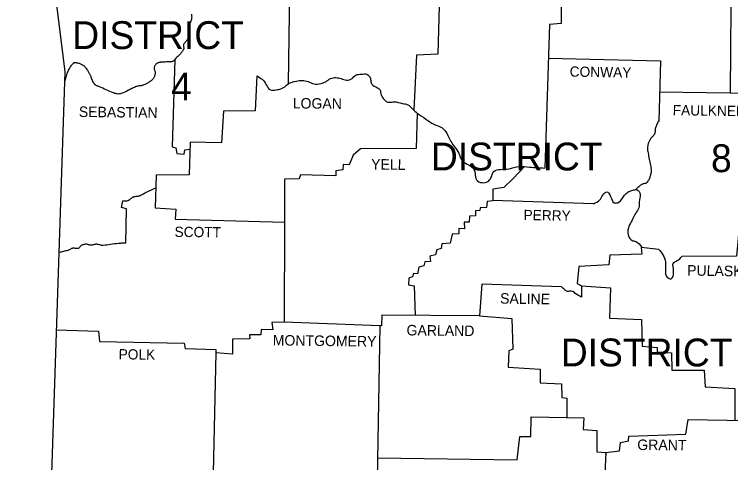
# Model space of a CAD drawing. Extents: x 1373878 to 1386598, y 1168333 to 1170533.
# Drawn here: x 1376295.6 to 1376588.9, y 1169955.3 to 1170138.8 of the extents above; entities that cross this region are included whole.
import ezdxf

# ---------------------------------------------------------------- set-up
doc = ezdxf.new("R2010")
doc.units = 0
doc.layers.add('1', color=7, linetype='Continuous')
doc.layers.add('Default', color=7, linetype='Continuous')

msp = doc.modelspace()

# ---------------------------------------------------------------- linework, layer by layer
at = {"layer": '1'}
msp.add_line((1376445.29, 1170011.31), (1376444.13, 1169948.51), dxfattribs=at)
for points in [[(1376295.59, 1170281.4), (1376316.29, 1170115.21), (1376307.29, 1169843.91)], [(1376599.19, 1170281.6), (1376599.39, 1170257.2), (1376597.69, 1170257.1), (1376597.99, 1170232.2), (1376590.99, 1170231.2), (1376591.59, 1170224.5), (1376593.99, 1170221.4), (1376593.79, 1170213.5), (1376580.19, 1170213), (1376579.69, 1170200.8), (1376567.29, 1170200.4), (1376566.69, 1170185.61), (1376567.39, 1170184.41), (1376567.69, 1170160.81), (1376589.09, 1170159.41), (1376588.79, 1170106.71), (1376605.79, 1170106.21), (1376605.79, 1170052.61), (1376592.39, 1170051.61), (1376591.39, 1170039.81), (1376568.89, 1170039.71)], [(1376408.49, 1170168.11), (1376407.79, 1170110.41)], [(1376394.89, 1170113.61), (1376394.19, 1170099.31), (1376381.19, 1170099.21), (1376380.49, 1170086.21), (1376367.59, 1170086.51), (1376367.19, 1170073.11), (1376353.69, 1170073.01), (1376353.29, 1170059.61), (1376361.79, 1170059.11), (1376361.49, 1170055.01), (1376406.23, 1170053.77)], [(1376406.23, 1170053.77), (1376406.09, 1170012.81), (1376401.09, 1170012.71), (1376401.49, 1170009.71), (1376396.69, 1170009.81), (1376396.59, 1170007.61), (1376391.89, 1170007.61), (1376391.99, 1170006.01), (1376384.99, 1170005.81), (1376384.89, 1169999.71), (1376378.09, 1170000.31), (1376376.99, 1169951.11), (1376338.49, 1169951.21), (1376337.59, 1169939.81), (1376338.99, 1169938.81), (1376338.89, 1169926.01), (1376310.06, 1169927.28)], [(1376559.49, 1170042.61), (1376552.29, 1170043.41), (1376552.59, 1170040.71), (1376539.49, 1170040.21), (1376539.09, 1170036.31), (1376526.79, 1170035.61), (1376526.09, 1170028.61), (1376527.89, 1170027.71), (1376527.89, 1170023.11)], [(1376519.69, 1170027.31), (1376486.99, 1170028.31), (1376486.09, 1170015.41), (1376446.09, 1170015.61), (1376445.93, 1170011.29)], [(1376537.79, 1169959.41), (1376543.39, 1169960.21), (1376543.79, 1169963.61), (1376547.09, 1169964.21), (1376547.29, 1169966.21), (1376570.59, 1169966.91), (1376571.49, 1169973.01), (1376595.39, 1169972.61)], [(1376537.79, 1169959.41), (1376536.59, 1169933.21), (1376535.69, 1169933.51), (1376535.79, 1169920.03)]]:
    msp.add_lwpolyline(points, dxfattribs=at)
for points in [[(1376394.89, 1170113.61), (1376397.09, 1170112.21), (1376398.79, 1170109.91), (1376400.29, 1170108.01), (1376402.79, 1170107.91), (1376404.79, 1170108.31), (1376407.79, 1170110.41)], [(1376559.49, 1170042.61), (1376561.19, 1170040.41), (1376562.19, 1170037.41), (1376562.19, 1170034.01), (1376562.99, 1170031.21), (1376564.59, 1170030.61), (1376565.59, 1170033.01), (1376565.39, 1170035.41), (1376565.39, 1170036.81), (1376567.09, 1170038.01), (1376568.89, 1170039.71)], [(1376527.89, 1170023.11), (1376525.29, 1170024.61), (1376523.79, 1170025.51), (1376522.19, 1170025.41), (1376520.89, 1170026.21), (1376519.69, 1170027.31)]]:
    msp.add_spline(points, degree=3, dxfattribs=at)
at = {"layer": 'Default'}
for points in [[(1376476.63, 1170162.03), (1376476.52, 1170142.44), (1376469.62, 1170142.34), (1376469.02, 1170122.44), (1376460.22, 1170122.14), (1376459.13, 1170099.7)], [(1376519.7, 1170161.68), (1376519.49, 1170135.11), (1376514.69, 1170134.71), (1376512.79, 1170075.91)], [(1376514.24, 1170120.81), (1376560.19, 1170119.71), (1376559.59, 1170095.01)], [(1376361.33, 1170120.28), (1376360.29, 1170084.61), (1376361.79, 1170084.21), (1376362.09, 1170081.81), (1376365.09, 1170081.61), (1376365.39, 1170083.31), (1376367.51, 1170083.66)], [(1376559.69, 1170107.11), (1376588.79, 1170106.71)], [(1376460.59, 1170098.31), (1376460.19, 1170083.91), (1376437.39, 1170083.81), (1376434.39, 1170081.21), (1376432.69, 1170077.21), (1376430.19, 1170077.41), (1376430.09, 1170075.11), (1376427.19, 1170074.81), (1376427.29, 1170072.71), (1376412.79, 1170073.11), (1376412.29, 1170071.51), (1376406.29, 1170071.31), (1376406.23, 1170053.77)], [(1376504.35, 1170076.44), (1376499.89, 1170071.61), (1376495.99, 1170067.91), (1376491.49, 1170067.21), (1376491.49, 1170062.51), (1376489.29, 1170062.21), (1376488.89, 1170059.81), (1376486.39, 1170059.61), (1376486.19, 1170058.51), (1376484.49, 1170058.41), (1376484.39, 1170056.31), (1376481.99, 1170056.21), (1376481.79, 1170053.81), (1376479.79, 1170053.81), (1376479.89, 1170051.01), (1376477.69, 1170051.21), (1376477.59, 1170049.01), (1376474.89, 1170048.81), (1376474.09, 1170045.21), (1376470.69, 1170044.91), (1376470.39, 1170042.91), (1376468.59, 1170042.41), (1376468.09, 1170040.31), (1376465.79, 1170039.81), (1376465.99, 1170037.71), (1376463.69, 1170037.51), (1376463.29, 1170035.91), (1376461.19, 1170035.31), (1376460.69, 1170032.61), (1376459.09, 1170032.71), (1376458.59, 1170031.31), (1376457.09, 1170030.81), (1376456.99, 1170028.11), (1376459.29, 1170027.71), (1376459.71, 1170015.54)], [(1376341.19, 1170045.11), (1376341.49, 1170059.21), (1376339.49, 1170059.81), (1376340.09, 1170062.51)], [(1376532.79, 1170061.31), (1376491.49, 1170062.61)], [(1376527.89, 1170027.65), (1376539.79, 1170026.91), (1376539.39, 1170014.41), (1376552.49, 1170013.91), (1376552.69, 1170003.01), (1376558.89, 1170002.51), (1376558.89, 1170000.61), (1376564.69, 1170000.21), (1376564.89, 1169993.21), (1376578.09, 1169993.21), (1376578.49, 1169986.31), (1376590.69, 1169985.71), (1376590.59, 1169972.69)], [(1376486.09, 1170015.41), (1376499.39, 1170014.31), (1376499.79, 1170001.71), (1376498.09, 1170001.11), (1376497.89, 1169994.41), (1376510.99, 1169993.51), (1376510.99, 1169988.01), (1376519.69, 1169987.51), (1376519.79, 1169982.01), (1376521.89, 1169981.71), (1376521.79, 1169973.81)], [(1376445.29, 1170011.31), (1376406.09, 1170012.81)], [(1376312.79, 1170009.71), (1376330.09, 1170009.11), (1376330.49, 1170004.91), (1376365.09, 1170004.21), (1376365.49, 1170002.01), (1376378.09, 1170001.61), (1376378.09, 1170000.31)], [(1376445.93, 1170011.29), (1376445.29, 1170011.31)], [(1376444.29, 1169957.31), (1376501.49, 1169956.51), (1376502.59, 1169966.01), (1376507.09, 1169966.01), (1376507.19, 1169974.01), (1376528.79, 1169973.71), (1376528.59, 1169968.91), (1376534.19, 1169968.51), (1376534.19, 1169959.71), (1376537.79, 1169959.41), (1376537.75, 1169958.5)]]:
    msp.add_lwpolyline(points, dxfattribs=at)
for points in [[(1376368.09, 1170138.81), (1376368.18, 1170138.28), (1376368.22, 1170137.75), (1376368.09, 1170136.71), (1376367.91, 1170136.15), (1376367.7, 1170135.61), (1376367.49, 1170135.06), (1376367.29, 1170134.51), (1376366.79, 1170132.61), (1376366.79, 1170131.99), (1376366.95, 1170131.36), (1376367.1, 1170130.73), (1376367.13, 1170130.42), (1376367.09, 1170130.11), (1376366.72, 1170129.08), (1376366.19, 1170128.11), (1376365.89, 1170127.69), (1376365.53, 1170127.31), (1376365.18, 1170126.92), (1376364.89, 1170126.51), (1376364.81, 1170126.03), (1376364.9, 1170125.51), (1376364.99, 1170124.98), (1376364.89, 1170124.51), (1376364.73, 1170124.23), (1376364.57, 1170123.95), (1376364.21, 1170123.41), (1376363.82, 1170122.89), (1376363.39, 1170122.41), (1376361.79, 1170120.81), (1376361.16, 1170120.09), (1376360.81, 1170119.76), (1376360.61, 1170119.62), (1376360.51, 1170119.56), (1376360.39, 1170119.51), (1376359.78, 1170119.34), (1376359.15, 1170119.3), (1376358.52, 1170119.31), (1376358.21, 1170119.32), (1376357.89, 1170119.31), (1376356.84, 1170119.26), (1376355.79, 1170119.21), (1376355.25, 1170119.15), (1376354.72, 1170119.04), (1376354.2, 1170118.84), (1376353.95, 1170118.69), (1376353.69, 1170118.51), (1376353.36, 1170118.18), (1376353.13, 1170117.81), (1376352.98, 1170117.42), (1376352.89, 1170117.01), (1376352.92, 1170116.43), (1376353.09, 1170115.86), (1376353.26, 1170115.28), (1376353.29, 1170114.71), (1376353.2, 1170114.14), (1376353.06, 1170113.58), (1376352.49, 1170112.51), (1376351.51, 1170111.54), (1376350.39, 1170110.81), (1376349.27, 1170110.19), (1376348.09, 1170109.71), (1376347.5, 1170109.58), (1376346.88, 1170109.53), (1376346.27, 1170109.47), (1376345.69, 1170109.31), (1376344.86, 1170108.92), (1376344.04, 1170108.52), (1376343.22, 1170108.11), (1376342.39, 1170107.71), (1376339.39, 1170106.41), (1376338.61, 1170106.22), (1376337.79, 1170106.21), (1376336.97, 1170106.35), (1376336.19, 1170106.61), (1376333.19, 1170107.91), (1376330.49, 1170109.11), (1376329.93, 1170109.34), (1376329.37, 1170109.59), (1376328.85, 1170109.89), (1376328.61, 1170110.08), (1376328.5, 1170110.19), (1376328.39, 1170110.31), (1376327.83, 1170111.17), (1376327.43, 1170112.11), (1376327.09, 1170113.07), (1376326.91, 1170113.55), (1376326.69, 1170114.01), (1376326.16, 1170115.01), (1376325.59, 1170116.01), (1376325.21, 1170116.57), (1376324.77, 1170117.09), (1376324.27, 1170117.56), (1376323.99, 1170117.79), (1376323.69, 1170118.01), (1376323.14, 1170118.32), (1376322.56, 1170118.54), (1376321.98, 1170118.69), (1376321.39, 1170118.81), (1376320.91, 1170118.9), (1376320.41, 1170118.95), (1376319.92, 1170118.88), (1376319.7, 1170118.78), (1376319.59, 1170118.7), (1376319.49, 1170118.61), (1376318.15, 1170116.82), (1376317.27, 1170114.96), (1376316.68, 1170113.05), (1376316.16, 1170111.11)], [(1376407.79, 1170110.41), (1376411.09, 1170111.51), (1376413.49, 1170111.71), (1376415.89, 1170111.31), (1376418.39, 1170110.31), (1376421.09, 1170110.51), (1376423.09, 1170111.21), (1376425.09, 1170112.51), (1376427.29, 1170112.91), (1376429.39, 1170112.51), (1376431.59, 1170111.91), (1376433.99, 1170112.61), (1376435.39, 1170113.91), (1376437.79, 1170114.31), (1376439.89, 1170114.31), (1376441.39, 1170112.61), (1376441.69, 1170110.81), (1376443.59, 1170109.11), (1376445.29, 1170108.01), (1376445.79, 1170105.91), (1376446.69, 1170104.41), (1376447.59, 1170103.41), (1376448.89, 1170102.81), (1376451.09, 1170103.01), (1376454.49, 1170102.31), (1376456.69, 1170101.81), (1376458.69, 1170100.11), (1376460.59, 1170098.31)], [(1376460.59, 1170098.31), (1376464.09, 1170095.91), (1376467.39, 1170093.81), (1376470.79, 1170092.31), (1376472.69, 1170090.11), (1376474.39, 1170086.71), (1376475.79, 1170084.61), (1376477.59, 1170082.01), (1376478.89, 1170079.11), (1376480.99, 1170077.51), (1376483.19, 1170076.11), (1376484.29, 1170073.61), (1376484.79, 1170071.11), (1376487.19, 1170069.91), (1376489.49, 1170070.41), (1376490.79, 1170071.91), (1376491.99, 1170074.51), (1376494.69, 1170075.31), (1376498.19, 1170075.61), (1376502.19, 1170076.51), (1376506.59, 1170076.31), (1376512.79, 1170075.91)], [(1376559.59, 1170095.01), (1376559.45, 1170095.05), (1376559.29, 1170094.92), (1376558.95, 1170094.31), (1376558.6, 1170093.48), (1376558.44, 1170093.07), (1376558.29, 1170092.71), (1376558.08, 1170091.95), (1376558, 1170091.18), (1376557.92, 1170090.42), (1376557.83, 1170090.06), (1376557.69, 1170089.71), (1376557.35, 1170089.2), (1376556.92, 1170088.75), (1376556.47, 1170088.3), (1376556.09, 1170087.81), (1376555.79, 1170087.28), (1376555.5, 1170086.74), (1376555.09, 1170085.61), (1376555.02, 1170085.25), (1376554.96, 1170084.88), (1376554.9, 1170084.15), (1376554.9, 1170083.43), (1376554.99, 1170082.71), (1376555.49, 1170080.11), (1376555.99, 1170077.61), (1376556.21, 1170076.46), (1376556.3, 1170075.88), (1376556.39, 1170075.31), (1376556.42, 1170074.58), (1376556.3, 1170073.86), (1376556.11, 1170073.13), (1376556, 1170072.77), (1376555.89, 1170072.41), (1376555.67, 1170071.73), (1376555.4, 1170071.08), (1376555.05, 1170070.47), (1376554.84, 1170070.18), (1376554.72, 1170070.04), (1376554.59, 1170069.91), (1376554.14, 1170069.63), (1376553.61, 1170069.51), (1376553.07, 1170069.41), (1376552.59, 1170069.21), (1376552.26, 1170068.97), (1376551.93, 1170068.74), (1376551.28, 1170068.25), (1376550.68, 1170067.7), (1376550.16, 1170067.09)], [(1376340.09, 1170062.51), (1376340.64, 1170062.43), (1376341.2, 1170062.44), (1376342.03, 1170062.61), (1376342.16, 1170062.66), (1376342.29, 1170062.71), (1376342.58, 1170062.85), (1376342.84, 1170063.02), (1376343.35, 1170063.42), (1376343.85, 1170063.81), (1376344.25, 1170064.05), (1376344.39, 1170064.11), (1376344.73, 1170064.21), (1376345.08, 1170064.28), (1376345.8, 1170064.37), (1376346.52, 1170064.48), (1376346.86, 1170064.58), (1376347.19, 1170064.71), (1376347.9, 1170065.07), (1376348.59, 1170065.47), (1376349.28, 1170065.85), (1376349.99, 1170066.21), (1376353.54, 1170067.83)], [(1376532.79, 1170061.31), (1376535.29, 1170062.71), (1376536.59, 1170064.81), (1376538.19, 1170066.11), (1376539.79, 1170064.31), (1376541.19, 1170061.71), (1376542.69, 1170061.71), (1376544.59, 1170063.51), (1376545.79, 1170065.11), (1376547.29, 1170066.31), (1376548.89, 1170066.81), (1376550.59, 1170067.01), (1376551.89, 1170065.11), (1376551.49, 1170062.11), (1376551.49, 1170060.11), (1376550.39, 1170058.01), (1376549.19, 1170055.81), (1376547.89, 1170053.31), (1376546.89, 1170050.61), (1376547.09, 1170048.01), (1376548.49, 1170046.31), (1376550.09, 1170045.81), (1376552.52, 1170043.38)], [(1376341.19, 1170045.11), (1376340.47, 1170045.12), (1376339.74, 1170045.11), (1376338.29, 1170045.01), (1376334.99, 1170044.61), (1376331.99, 1170044.21), (1376331.65, 1170044.2), (1376331.32, 1170044.24), (1376330.64, 1170044.41), (1376329.97, 1170044.6), (1376329.46, 1170044.7), (1376329.29, 1170044.71), (1376328.67, 1170044.66), (1376328.04, 1170044.52), (1376327.41, 1170044.37), (1376326.79, 1170044.31), (1376326.37, 1170044.37), (1376325.94, 1170044.51), (1376325.52, 1170044.64), (1376325.09, 1170044.71), (1376324.57, 1170044.68), (1376324.04, 1170044.58), (1376323.52, 1170044.42), (1376322.99, 1170044.21), (1376322.65, 1170043.95), (1376322.38, 1170043.59), (1376322.13, 1170043.24), (1376321.79, 1170043.01), (1376321.5, 1170042.94), (1376321.19, 1170042.93), (1376320.54, 1170043), (1376319.9, 1170043.08), (1376319.44, 1170043.05), (1376319.29, 1170043.01), (1376318.84, 1170042.82), (1376318.4, 1170042.6), (1376317.96, 1170042.38), (1376317.49, 1170042.21), (1376316.59, 1170041.95), (1376315.68, 1170041.71), (1376314.77, 1170041.53), (1376313.84, 1170041.39)]]:
    msp.add_spline(points, degree=3, dxfattribs=at)

# ---------------------------------------------------------------- texts
for s, p in [('DISTRICT', (1376319.31, 1170124.59)), ('4', (1376359.81, 1170103.59)), ('DISTRICT', (1376466.19, 1170074.91)), ('8', (1376580.89, 1170074.21)), ('DISTRICT 6', (1376519.39, 1169994.71))]:
    msp.add_text(s, height=11.4, dxfattribs=at).set_placement(p)
for s, height, rotation, p in [('CONWAY', 4.199, 359.0372, (1376522.99, 1170113.31)), ('LOGAN', 4.301, 359.3969, (1376409.59, 1170100.31)), ('SEBASTIAN', 4.299, 359.2816, (1376321.99, 1170096.81)), ('FAULKNER', 4.2, 359.2486, (1376565.19, 1170097.51)), ('YELL', 4.301, 359.1987, (1376441.69, 1170075.31)), ('PERRY', 4.2, 359.0858, (1376504.09, 1170054.61)), ('SCOTT', 4.2, 359.4063, (1376361.19, 1170047.71)), ('PULASKI', 4.301, 359.0531, (1376571.09, 1170031.91)), ('SALINE', 4.301, 359.1492, (1376494.49, 1170020.41)), ('GARLAND', 4.301, 359.3658, (1376456.19, 1170007.41)), ('MONTGOMERY', 4.301, 359.2944, (1376401.39, 1170003.31)), ('POLK', 4.199, 359.2152, (1376338.29, 1169997.61)), ('GRANT', 4.301, 359.4032, (1376550.69, 1169960.51))]:
    msp.add_text(s, height=height, rotation=rotation, dxfattribs=at).set_placement(p)

doc.saveas('drawing.dxf')
